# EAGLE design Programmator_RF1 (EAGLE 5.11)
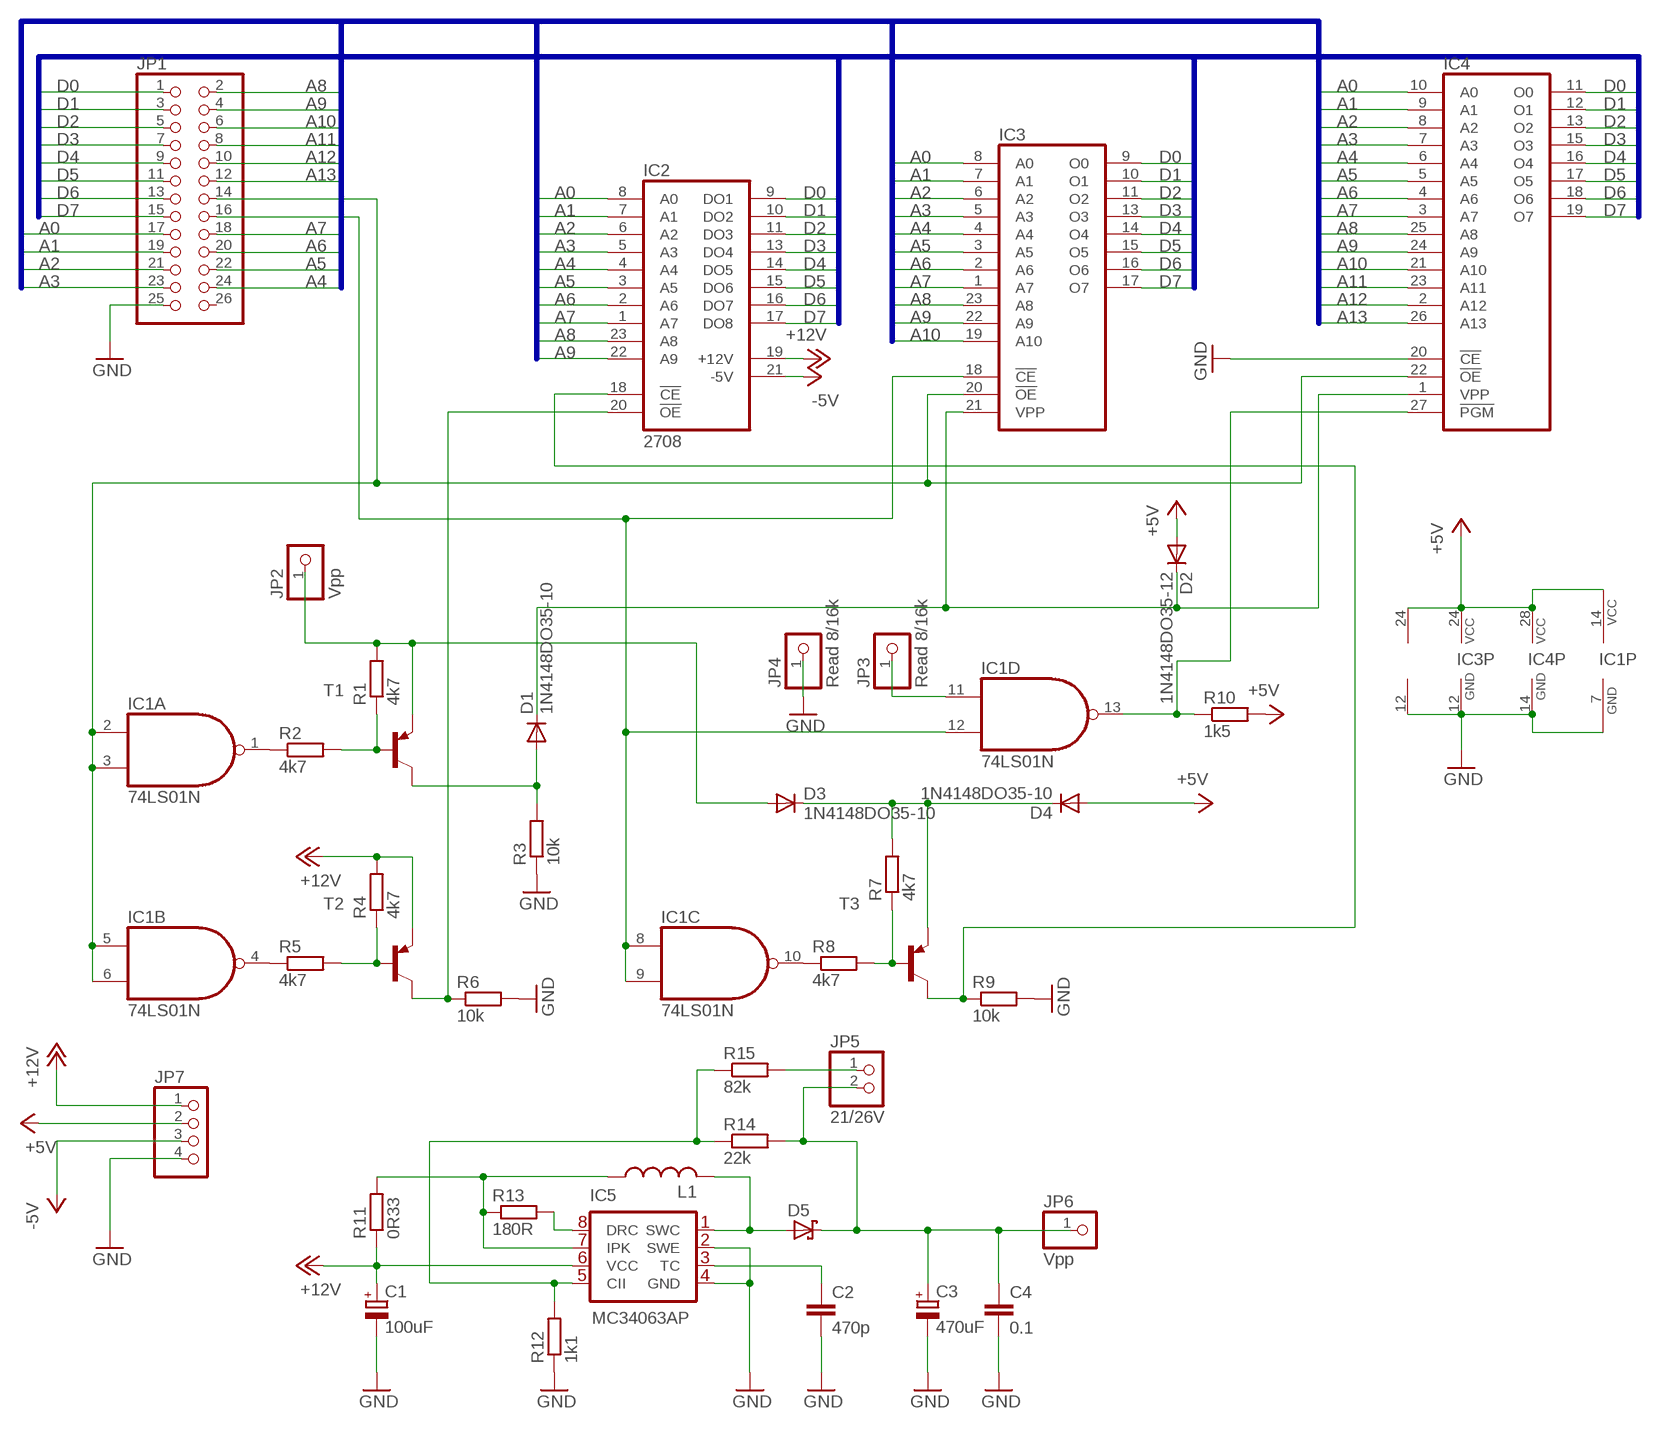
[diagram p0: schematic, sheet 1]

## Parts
C1  100uF  CPOL-EUE2.5-5  [E2,5-5]
C2  470p  C-EU025-024X044  [C025-024X044]
C3  470uF  CPOL-EUE2.5-5  [E2,5-5]
C4  0.1  C-EU025-024X044  [C025-024X044]
D1  1N4148DO35-10  [DO35-10]
D2  1N4148DO35-12  [DO35-12]
D3  1N4148DO35-10  [DO35-10]
D4  1N4148DO35-10  [DO35-10]
D5  SCHOTTKY-DIODEF126Z12  [F126Z12]
IC1  74LS01N  [DIL14]
IC2  2708  [DIL24-6]
IC3  2716  [DIL24]
IC4  27128  [DIL28]
IC5  MC34063AP  [DIL08]
JP1  PINHD-2X13  [2X13]
JP2  Vpp  PINHD-1X1  [1X01]
JP3  Read 8/16k  PINHD-1X1  [1X01]
JP4  Read 8/16k  PINHD-1X1  [1X01]
JP5  21/26V  PINHD-1X2  [1X02]
JP6  Vpp  PINHD-1X1  [1X01]
JP7  PINHD-1X4  [1X04]
L1  L-US0207/10  [0207/10]
R1  4k7  R-EU_0207/10  [0207/10]
R2  4k7  R-EU_0207/10  [0207/10]
R3  10k  R-EU_0207/10  [0207/10]
R4  4k7  R-EU_0207/10  [0207/10]
R5  4k7  R-EU_0207/10  [0207/10]
R6  10k  R-EU_0207/10  [0207/10]
R7  4k7  R-EU_0207/10  [0207/10]
R8  4k7  R-EU_0207/10  [0207/10]
R9  10k  R-EU_0207/10  [0207/10]
R10  1k5  R-EU_0207/10  [0207/10]
R11  0R33  R-EU_0207/10  [0207/10]
R12  1k1  R-EU_0207/10  [0207/10]
R13  180R  R-EU_0207/10  [0207/10]
R14  22k  R-EU_0207/10  [0207/10]
R15  82k  R-EU_0207/10  [0207/10]
T1  -PNP-TO92-CBE  [TO92-CBE]
T2  -PNP-TO92-CBE  [TO92-CBE]
T3  -PNP-TO92-CBE  [TO92-CBE]

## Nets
+5V: D2.A D4.A IC1.14(P:VCC) IC2.24(V+) IC3.24(VCC) IC4.28(VCC) JP7.2 R10.2
+12V: C1.+ IC2.19(+12V) IC5.6(VCC) JP7.1 R4.2 R11.1 T2.E
-5V: IC2.21(-5V) JP7.3
A0: IC2.8(A0) IC3.8(A0) IC4.10(A0) JP1.17
A1: IC2.7(A1) IC3.7(A1) IC4.9(A1) JP1.19
A2: IC2.6(A2) IC3.6(A2) IC4.8(A2) JP1.21
A3: IC2.5(A3) IC3.5(A3) IC4.7(A3) JP1.23
A4: IC2.4(A4) IC3.4(A4) IC4.6(A4) JP1.24
A5: IC2.3(A5) IC3.3(A5) IC4.5(A5) JP1.22
A6: IC2.2(A6) IC3.2(A6) IC4.4(A6) JP1.20
A7: IC2.1(A7) IC3.1(A7) IC4.3(A7) JP1.18
A8: IC2.23(A8) IC3.23(A8) IC4.25(A8) JP1.2
A9: IC2.22(A9) IC3.22(A9) IC4.24(A9) JP1.4
A10: IC3.19(A10) IC4.21(A10) JP1.6
A11: IC4.23(A11) JP1.8
A12: IC4.2(A12) JP1.10
A13: IC4.26(A13) JP1.12
D0: IC2.9(DO1) IC3.9(O0) IC4.11(O0) JP1.1
D1: IC2.10(DO2) IC3.10(O1) IC4.12(O1) JP1.3
D2: IC2.11(DO3) IC3.11(O2) IC4.13(O2) JP1.5
D3: IC2.13(DO4) IC3.13(O3) IC4.15(O3) JP1.7
D4: IC2.14(DO5) IC3.14(O4) IC4.16(O4) JP1.9
D5: IC2.15(DO6) IC3.15(O5) IC4.17(O5) JP1.11
D6: IC2.16(DO7) IC3.16(O6) IC4.18(O6) JP1.13
D7: IC2.17(DO8) IC3.17(O7) IC4.19(O7) JP1.15
GND: C1.- C2.2 C3.- C4.2 IC1.7(P:GND) IC2.12(GND) IC3.12(GND) IC4.14(GND) IC4.20(!CE) IC5.2(SWE) IC5.4(GND) JP1.25 JP4.1 JP7.4 R3.1 R6.2 R9.2 R12.1
N$2: R1.1 R2.2 T1.B
N$3: R4.1 R5.2 T2.B
N$4: R7.1 R8.2 T3.B
N$5: D1.A R3.2 T1.C
N$6: IC1.1(A:O) R2.1
N$7: IC1.13(D:O) IC4.27(!PGM) R10.1
N$8: IC1.4(B:O) R5.1
N$9: IC1.10(C:O) R8.1
N$10: D3.C D4.C R7.2 T3.E
N$11: IC2.18(!CE) R9.1 T3.C
N$12: IC2.20(!OE) R6.1 T2.C
N$13: IC5.7(IPK) L1.1 R11.2 R13.1
N$14: IC1.11(D:I0) JP3.1
N$15: D1.C D2.C IC3.21(VPP) IC4.1(VPP)
N$16: D3.A JP2.1 R1.2 T1.E
N$17: IC1.2(A:I0) IC1.3(A:I1) IC1.5(B:I0) IC1.6(B:I1) IC3.20(!OE) IC4.22(!OE) JP1.14
N$19: IC1.8(C:I0) IC1.9(C:I1) IC1.12(D:I1) IC3.18(!CE) JP1.16
N$20: IC5.5(CII) R12.2 R14.1 R15.1
N$21: IC5.8(DRC) R13.2
N$22: JP5.1 R15.2
N$23: C3.+ C4.1 D5.C JP5.2 JP6.1 R14.2
N$25: C2.1 IC5.3(TC)
N$28: D5.A IC5.1(SWC) L1.2
Unconnected: JP1.26

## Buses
A[0..13]
D[0..7]

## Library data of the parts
C1 C3 = rcl:CPOL-EU: POLARIZED CAPACITOR, European symbol
C2 C4 = rcl:C-EU: CAPACITOR, European symbol
D1-D4 = alex1:1N4148: DIODE
D5 = diode:SCHOTTKY-DIODE: Schottky Diode
IC1 = 74xx-us:74*01: Quad 2-input NAND gate, open collector
IC2 = alex1:2708
IC3 = memory:2716: MEMORY
IC4 = alex1:27128: MEMORY
IC5 = alex1:MC34063A*
JP1 = pinhead:PINHD-2X13: PIN HEADER
JP2-JP4 JP6 = pinhead:PINHD-1X1: PIN HEADER
JP5 = pinhead:PINHD-1X2: PIN HEADER
JP7 = pinhead:PINHD-1X4: PIN HEADER
L1 = rcl:L-US: INDUCTOR, American symbol
R1-R15 = rcl:R-EU_: RESISTOR, European symbol
T1-T3 = transistor-neu-to92:*-PNP-: PNP Transistror

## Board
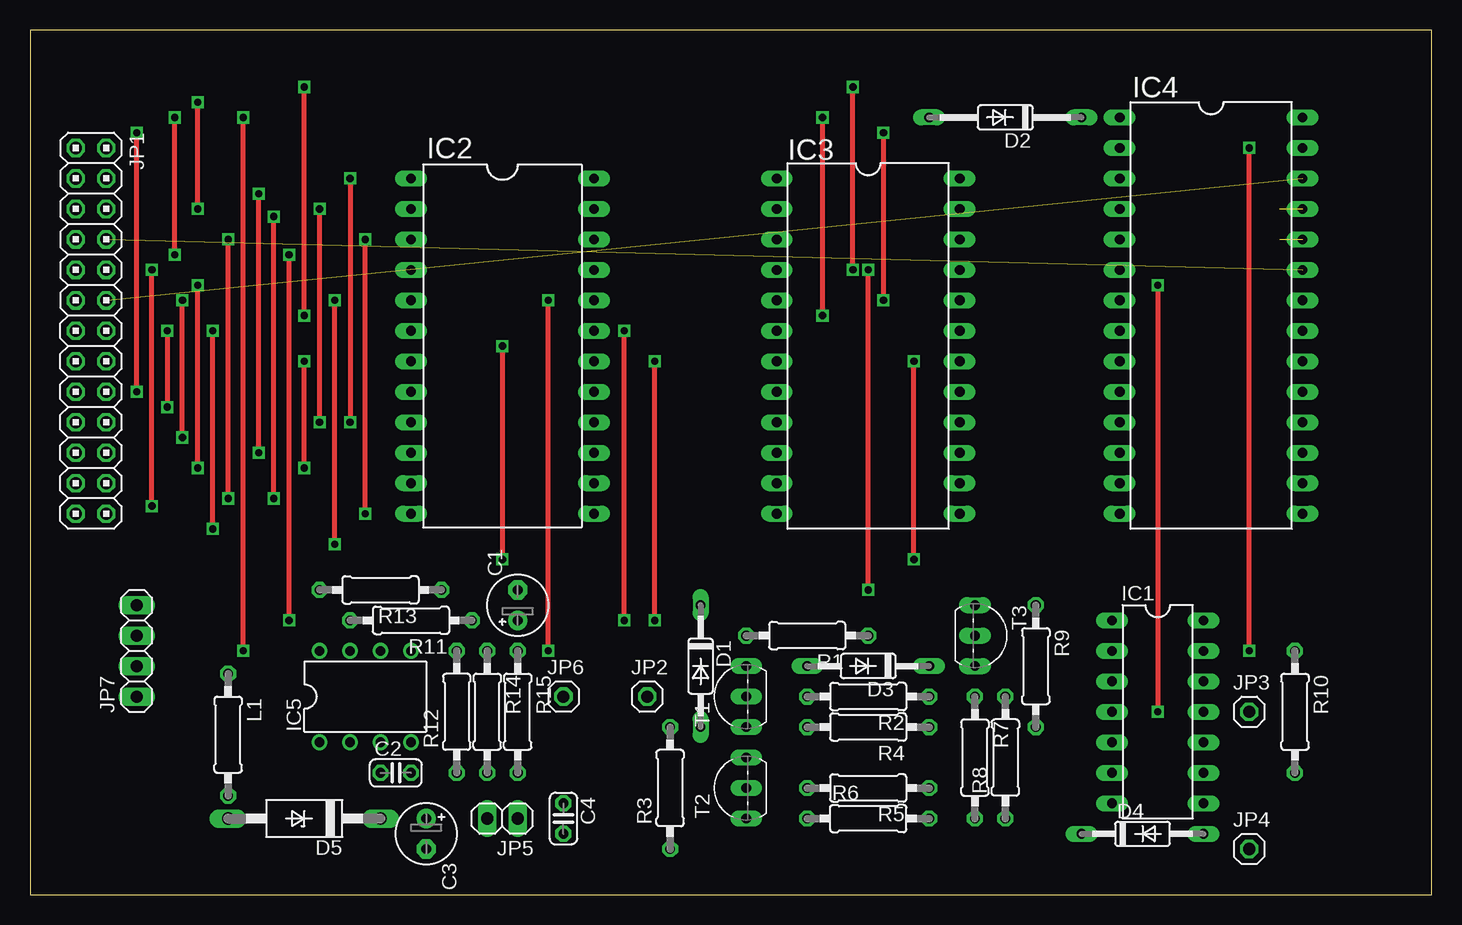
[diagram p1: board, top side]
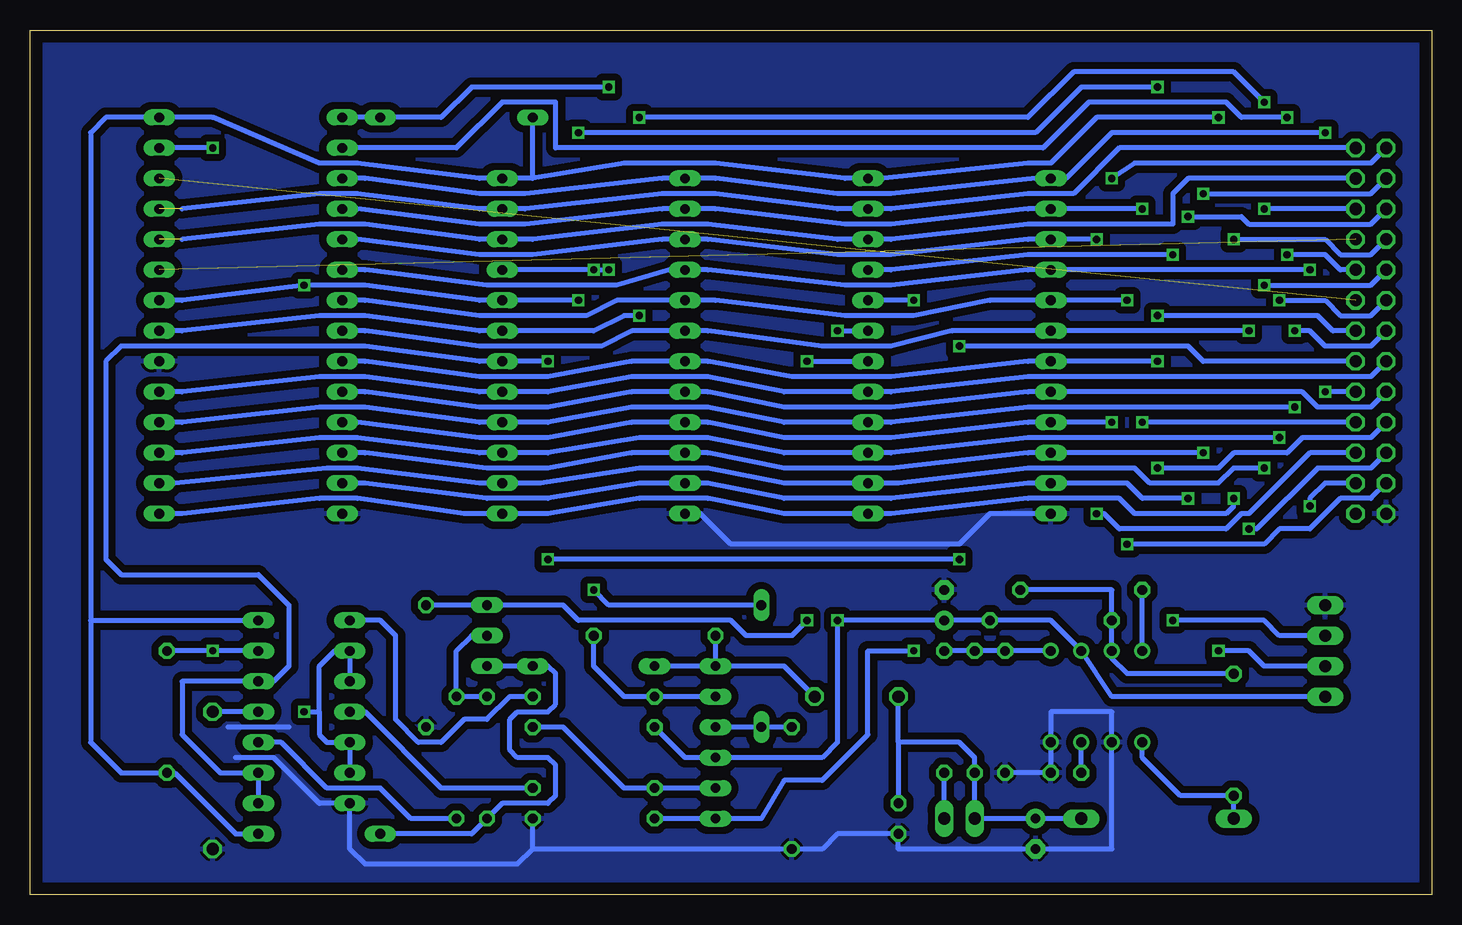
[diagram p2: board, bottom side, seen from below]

Size 116.82 x 72.06 mm. Coordinates in mm from the lower left corner, seen from the top.
Outline: 0,0 116.82,0 116.82,72.06 0,72.06 0,0
Copper layers (1*16): Top 0.035mm / dielectric 1.5mm / Bottom 0.035mm
Design rules "default": minimum track width 10mil, minimum drill 24mil, track to track 8mil, track to pad 8mil, pad to pad 8mil, via to via 8mil, smd to smd 8mil, copper to edge 40mil, drill to drill 8mil, minimum pad ring 10mil, minimum via ring 8mil, stop-mask expansion 4mil, vias tented up to drill 0mil, thermal gap 10mil

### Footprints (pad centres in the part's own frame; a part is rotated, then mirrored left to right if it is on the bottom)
E2,5-5 = drill 0.813 pad 1.6 round: + -1.27,0 | drill 0.813 pad 1.6 octagon: - 1.27,0
C025-024X044 = drill 0.813 octagon: 1 -1.27,0; 2 1.27,0
DO35-10 = drill 0.813 long: A 5.08,0; C -5.08,0
DO35-12 = drill 0.813 long: A 6.35,0; C -6.35,0
F126Z12 = drill 1.016 long: A 6.35,0; C -6.35,0
DIL14 = drill 0.813 long: 1 -7.62,-3.81; 2 -5.08,-3.81; 3 -2.54,-3.81; 4 0,-3.81; 5 2.54,-3.81; 6 5.08,-3.81; 7 7.62,-3.81; 8 7.62,3.81; 9 5.08,3.81; 10 2.54,3.81; 11 0,3.81; 12 -2.54,3.81; 13 -5.08,3.81; 14 -7.62,3.81
DIL24-6 = drill 0.813 long: 1 -13.97,-7.62; 2 -11.43,-7.62; 3 -8.89,-7.62; 4 -6.35,-7.62; 5 -3.81,-7.62; 6 -1.27,-7.62; 7 1.27,-7.62; 8 3.81,-7.62; 9 6.35,-7.62; 10 8.89,-7.62; 11 11.43,-7.62; 12 13.97,-7.62; 13 13.97,7.62; 14 11.43,7.62; 15 8.89,7.62; 16 6.35,7.62; 17 3.81,7.62; 18 1.27,7.62; 19 -1.27,7.62; 20 -3.81,7.62; 21 -6.35,7.62; 22 -8.89,7.62; 23 -11.43,7.62; 24 -13.97,7.62
DIL24 = drill 0.813 long: 1 -13.97,-7.62; 2 -11.43,-7.62; 3 -8.89,-7.62; 4 -6.35,-7.62; 5 -3.81,-7.62; 6 -1.27,-7.62; 7 1.27,-7.62; 8 3.81,-7.62; 9 6.35,-7.62; 10 8.89,-7.62; 11 11.43,-7.62; 12 13.97,-7.62; 13 13.97,7.62; 14 11.43,7.62; 15 8.89,7.62; 16 6.35,7.62; 17 3.81,7.62; 18 1.27,7.62; 19 -1.27,7.62; 20 -3.81,7.62; 21 -6.35,7.62; 22 -8.89,7.62; 23 -11.43,7.62; 24 -13.97,7.62
DIL28 = drill 0.813 long: 1 -16.51,-7.62; 2 -13.97,-7.62; 3 -11.43,-7.62; 4 -8.89,-7.62; 5 -6.35,-7.62; 6 -3.81,-7.62; 7 -1.27,-7.62; 8 1.27,-7.62; 9 3.81,-7.62; 10 6.35,-7.62; 11 8.89,-7.62; 12 11.43,-7.62; 13 13.97,-7.62; 14 16.51,-7.62; 15 16.51,7.62; 16 13.97,7.62; 17 11.43,7.62; 18 8.89,7.62; 19 6.35,7.62; 20 3.81,7.62; 21 1.27,7.62; 22 -1.27,7.62; 23 -3.81,7.62; 24 -6.35,7.62; 25 -8.89,7.62; 26 -11.43,7.62; 27 -13.97,7.62; 28 -16.51,7.62
DIL08 = drill 0.813 pad 1.27 round: 1 -3.81,-3.81; 2 -1.27,-3.81; 3 1.27,-3.81; 4 3.81,-3.81; 5 3.81,3.81; 6 1.27,3.81; 7 -1.27,3.81; 8 -3.81,3.81
2X13 = drill 1.016 octagon: 1 -15.24,-1.27; 2 -15.24,1.27; 3 -12.7,-1.27; 4 -12.7,1.27; 5 -10.16,-1.27; 6 -10.16,1.27; 7 -7.62,-1.27; 8 -7.62,1.27; 9 -5.08,-1.27; 10 -5.08,1.27; 11 -2.54,-1.27; 12 -2.54,1.27; 13 0,-1.27; 14 0,1.27; 15 2.54,-1.27; 16 2.54,1.27; 17 5.08,-1.27; 18 5.08,1.27; 19 7.62,-1.27; 20 7.62,1.27; 21 10.16,-1.27; 22 10.16,1.27; 23 12.7,-1.27; 24 12.7,1.27; 25 15.24,-1.27; 26 15.24,1.27
1X01 = drill 1.016 octagon: 1 0,0
1X02 = drill 1.016 long: 1 -1.27,0; 2 1.27,0
1X04 = drill 1.016 long: 1 -3.81,0; 2 -1.27,0; 3 1.27,0; 4 3.81,0
0207/10 = drill 0.813 octagon: 1 -5.08,0; 2 5.08,0
TO92-CBE = drill 0.813 long: B 0,0; C -2.54,0; E 2.54,0

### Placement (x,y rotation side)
C1  40.64,24.13 90 top
C2  30.48,10.16 0 top
C3  33.02,5.08 270 top
C4  44.45,6.35 270 top
D1  55.88,19.05 270 top
D2  81.28,64.77 180 top
D3  69.85,19.05 180 top
D4  92.71,5.08 0 top
D5  22.86,6.35 180 top
IC1  93.98,15.24 270 top
IC2  39.37,45.72 270 top
IC3  69.85,45.72 270 top
IC4  98.42,48.26 270 top
IC5  27.94,16.51 0 top
JP1  5.08,46.99 270 top
JP2  51.43,16.51 0 top
JP3  101.6,15.24 0 top
JP4  101.6,3.81 0 top
JP5  39.37,6.35 180 top
JP6  44.45,16.51 0 top
JP7  8.89,20.32 90 top
L1  16.51,13.33 270 top
R1  64.77,21.59 180 top
R2  69.85,16.51 180 top
R3  53.34,8.89 90 top
R4  69.85,13.97 180 top
R5  69.85,8.89 180 top
R6  69.85,6.35 0 top
R7  78.74,11.43 270 top
R8  81.28,11.43 90 top
R9  83.82,19.05 270 top
R10  105.41,15.24 270 top
R11  31.75,22.86 180 top
R12  35.56,15.24 90 top
R13  29.21,25.4 180 top
R14  38.1,15.24 270 top
R15  40.64,15.24 270 top
T1  59.69,16.51 90 top
T2  59.69,8.89 90 top
T3  78.74,21.59 270 top

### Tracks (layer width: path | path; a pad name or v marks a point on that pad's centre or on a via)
+5V  (via drill 0.6)
  Top 0.406: v17.78,20.32 v17.78,64.77
  Bottom 0.406: 74.93,59.69 67.31,60.96 59.69,60.96 48.89,59.69 IC2.24 45.72,59.69 33.65,60.96 31.75,60.96 27.94,64.77 v17.78,64.77 | 74.93,59.69 IC3.24 79.38,59.69 89.54,60.96 92.71,60.96 101.6,64.77 IC4.28 110.49,64.77 111.76,63.5 111.76,22.86 | 111.76,22.86 111.76,12.7 109.22,10.16 R10.2 104.78,10.16 99.7,5.08 D4.A | v17.78,20.32 15.24,20.32 13.97,19.05 JP7.2 7.62,19.05 | 74.93,59.69 D2.A | 111.76,22.86 IC1.14
+12V  (via drill 0.6)
  Top 0.406: v49.53,22.86 v49.53,46.99
  Bottom 0.406: R4.2 62.23,11.43 T2.E 50.8,11.43 49.53,12.7 v49.53,22.86 C1.+ R11.1 31.75,22.86 IC5.6 26.67,16.51 JP7.1 | v49.53,46.99 IC2.19
-5V  (via drill 0.6)
  Top 0.406: v21.59,22.86 v21.59,53.34
  Bottom 0.406: IC2.21 45.08,52.07 33.65,53.34 v21.59,53.34 | JP7.3 12.7,21.59 13.97,22.86 v21.59,22.86
A0
  Bottom 0.406: IC2.8 33.65,41.91 45.08,40.64 53.97,40.64 60.32,41.91 IC3.8 66.67,41.91 73.66,40.64 79.38,40.64 88.9,41.91 IC4.10 | IC2.8 30.48,41.91 | JP1.17 5.08,40.64 9.53,40.64 10.79,41.91 IC2.8
A1  (via drill 0.6)
  Top 0.406: v22.86,35.56 v22.86,44.45
  Bottom 0.406: v22.86,44.45 IC2.7 33.65,44.45 45.08,43.18 53.34,43.18 60.32,44.45 IC3.7 66.67,44.45 73.66,43.18 79.38,43.18 88.9,44.45 IC4.9 | JP1.19 5.08,38.1 10.79,38.1 12.07,36.83 16.51,36.83 17.78,35.56 v22.86,35.56
A2  (via drill 0.6)
  Top 0.406: v15.24,30.48 v15.24,46.99
  Bottom 0.406: IC4.8 88.9,46.99 79.38,45.72 69.22,45.72 66.67,46.99 IC3.6 60.32,46.99 50.8,45.72 45.08,45.72 40,46.99 IC2.6 v15.24,46.99 | JP1.21 5.08,35.56 9.53,35.56 14.61,30.48 v15.24,30.48
A3  (via drill 0.6)
  Top 0.406: v25.4,29.21 v25.4,49.53
  Bottom 0.406: v25.4,49.53 IC2.5 36.83,49.53 43.18,48.26 48.89,48.26 59.69,49.53 IC3.5 67.95,49.53 70.48,48.26 79.38,48.26 88.9,49.53 IC4.7 | JP1.23 5.08,33.02 7.62,33.02 10.16,30.48 12.7,30.48 13.97,29.21 v25.4,29.21
A4  (via drill 0.6)
  Top 0.406: v10.16,32.39 v10.16,52.07
  Bottom 0.406: v10.16,52.07 IC2.4 33.65,52.07 45.08,50.8 48.89,50.8 60.32,52.07 IC3.4 63.5,52.07 67.95,50.8 78.74,50.8 88.9,52.07 IC4.6 | JP1.24 8.89,34.29 10.16,33.02 v10.16,32.39
A5  (via drill 0.6)
  Top 0.406: v27.94,31.75 v27.94,54.61
  Bottom 0.406: v27.94,54.61 IC2.3 33.65,54.61 45.08,53.34 49.53,53.34 60.32,54.61 IC3.3 64.14,54.61 74.93,53.34 79.38,53.34 89.54,54.61 IC4.5 | JP1.22 10.16,36.83 15.24,31.75 15.88,31.75 17.14,30.48 26.04,30.48 27.3,31.75 v27.94,31.75
A6  (via drill 0.6)
  Top 0.406: v24.13,39.37 v24.13,57.15
  Bottom 0.406: v24.13,57.15 IC2.2 33.65,57.15 45.08,55.88 48.89,55.88 59.69,57.15 IC3.2 64.14,57.15 75.56,55.88 79.38,55.88 89.54,57.15 IC4.4 | JP1.20 v24.13,39.37
A7  (via drill 0.6)
  Top 0.406: v8.89,41.91 v8.89,63.5
  Bottom 0.406: IC4.3 88.9,59.69 79.38,58.42 75.56,58.42 64.14,59.69 IC3.1 59.69,59.69 49.53,58.42 45.08,58.42 33.02,59.69 IC2.1 30.48,59.69 26.67,63.5 v8.89,63.5 | JP1.18 v8.89,41.91
A8  (1 unrouted)
  Bottom 0.406: 104.14,57.15 92.71,58.42 89.54,58.42 79.38,57.15 IC3.23 75.56,57.15 64.14,58.42 59.69,58.42 49.53,57.15 IC2.23 45.08,57.15 33.65,58.42 29.84,58.42 26.04,62.23 JP1.2
A9  (1 unrouted)
  Bottom 0.406: 104.14,54.61 92.71,55.88 88.9,55.88 79.38,54.61 IC3.22 74.93,54.61 64.14,55.88 60.32,55.88 49.53,54.61 IC2.22 45.08,54.61 33.65,55.88 21.59,55.88 21.59,58.42 20.32,59.69 JP1.4
A10  (via drill 0.6)
  Top 0.406: v13.97,57.15 v13.97,66.04 | v66.04,64.77 v66.04,48.26
  Bottom 0.406: IC3.19 79.38,46.99 88.9,48.26 92.71,48.26 104.14,46.99 IC4.21 | IC3.19 76.2,46.99 | v13.97,66.04 16.51,68.58 29.84,68.58 33.65,64.77 v66.04,64.77 | v66.04,48.26 67.31,48.26 69.85,46.99 IC3.19 | JP1.6 v13.97,57.15
A11  (1 unrouted)
A12  (via drill 0.6)
  Top 0.406: v12.07,53.34 v12.07,64.77
  Bottom 0.406: v12.07,64.77 15.88,64.77 17.14,66.04 28.57,66.04 32.38,62.23 73.03,62.23 73.03,66.04 77.47,66.04 81.28,62.23 IC4.2 | JP1.10 7.62,52.07 8.89,53.34 v12.07,53.34
A13  (1 unrouted)
D0  (via drill 0.6)
  Top 0.406: v26.67,59.69 v26.67,39.37
  Bottom 0.406: v26.67,39.37 IC2.9 33.65,39.37 45.08,38.1 53.97,38.1 60.32,39.37 IC3.9 66.67,39.37 73.66,38.1 79.38,38.1 89.54,39.37 IC4.11 | JP1.1 5.08,60.96 24.77,60.96 v26.67,59.69
D1  (via drill 0.6)
  Top 0.406: v19.05,36.83 v19.05,58.42
  Bottom 0.406: v19.05,36.83 IC2.10 33.65,36.83 45.08,35.56 53.97,35.56 60.32,36.83 IC3.10 66.67,36.83 73.66,35.56 78.74,35.56 88.9,36.83 IC4.12 | JP1.3 5.08,58.42 v19.05,58.42
D2  (via drill 0.6)
  Top 0.406: v20.32,33.02 v20.32,56.52
  Bottom 0.406: IC4.13 88.9,34.29 78.74,33.02 73.66,33.02 66.04,34.29 IC3.11 60.32,34.29 53.97,33.02 45.08,33.02 33.65,34.29 IC2.11 25.4,34.29 24.13,33.02 v20.32,33.02 | JP1.5 5.08,55.88 15.24,55.88 15.88,56.52 v20.32,56.52
D3  (via drill 0.6)
  Top 0.406: v16.51,33.02 v16.51,54.61
  Bottom 0.406: IC4.15 104.14,31.75 92.71,33.02 89.54,33.02 80.65,31.75 IC3.13 73.66,31.75 66.04,33.02 60.32,33.02 53.97,31.75 IC2.13 45.08,31.75 33.65,33.02 26.04,33.02 24.77,31.75 17.14,31.75 16.51,32.39 v16.51,33.02 | JP1.7 5.08,53.34 7.62,53.34 8.89,54.61 v16.51,54.61
D4  (via drill 0.6)
  Top 0.406: v13.97,35.56 v13.97,50.8
  Bottom 0.406: IC4.16 104.78,34.29 92.08,35.56 89.54,35.56 79.38,34.29 IC3.14 74.3,34.29 66.04,35.56 60.32,35.56 53.97,34.29 IC2.14 44.45,34.29 33.65,35.56 24.77,35.56 23.5,34.29 17.78,34.29 16.51,35.56 v13.97,35.56 | JP1.9 5.08,50.8 v13.97,50.8
D5  (via drill 0.6)
  Top 0.406: v12.7,38.1 v12.7,49.53
  Bottom 0.406: v12.7,38.1 33.65,38.1 45.08,36.83 IC2.15 53.97,36.83 60.32,38.1 66.04,38.1 73.66,36.83 IC3.15 79.38,36.83 89.54,38.1 92.71,38.1 104.14,36.83 IC4.17 | JP1.11 5.08,48.26 7.62,48.26 8.89,49.53 v12.7,49.53
D6  (via drill 0.6)
  Top 0.406: v11.43,46.99 v11.43,40.64
  Bottom 0.406: v11.43,40.64 33.65,40.64 45.08,39.37 IC2.16 53.97,39.37 60.32,40.64 66.67,40.64 73.66,39.37 IC3.16 79.38,39.37 88.9,40.64 92.71,40.64 104.14,39.37 IC4.18 | JP1.13 5.08,45.72 8.89,45.72 10.16,46.99 v11.43,46.99
D7
  Bottom 0.406: IC4.19 104.14,41.91 92.71,43.18 88.9,43.18 79.38,41.91 IC3.17 73.66,41.91 66.67,43.18 60.32,43.18 53.97,41.91 IC2.17 45.08,41.91 33.65,43.18 5.08,43.18 JP1.15
GND
  Bottom 0.406: IC2.12 36.83,31.75 39.37,29.21 58.42,29.21 60.96,31.75 IC3.12 | 74.93,3.81 76.2,2.54 88.9,2.54 90.17,3.81 IC1.7 92.71,7.62 96.52,11.43 99.7,11.43 | 74.93,3.81 R3.1 50.8,3.81 49.53,5.08 C4.2 44.45,3.81 C3.- 26.67,3.81 IC5.2 26.67,15.24 31.75,15.24 IC5.4 C2.2 R12.1 | 74.93,3.81 R6.2 | 95.25,13.97 100.33,13.97
  pour Bottom (isolate 0.61): 0,72.39 116.84,72.39 116.84,0 0,0
N$2
  Bottom 0.406: T1.B R2.2 67.31,16.51 69.85,19.05 R1.1
N$3
  Bottom 0.406: T2.B R5.2 67.31,8.89 72.39,13.97 R4.1
N$4
  Bottom 0.406: R7.1 R8.2 81.28,20.32 80.01,21.59 T3.B
N$5
  Bottom 0.406: D1.A R3.2 T1.C
N$6
  Bottom 0.406: R2.1 76.84,16.51 78.74,14.6 80.65,14.6 82.55,12.7 84.45,12.7 86.36,14.6 86.36,21.59 87.63,22.86 IC1.1
N$7  (via drill 0.6)
  Top 0.406: v101.6,20.32 v101.6,62.23
  Bottom 0.406: IC1.13 v101.6,20.32 R10.1 | v101.6,62.23 IC4.27
N$8
  Bottom 0.406: R5.1 82.55,8.89 88.9,15.24 IC1.4
N$9
  Bottom 0.406: R8.1 85.09,6.35 87.63,8.89 92.08,8.89 95.89,12.7 IC1.10 98.42,12.7
N$10
  Bottom 0.406: D4.C 80.01,5.08 R7.2 77.47,7.62 73.66,7.62 73.03,8.26 73.03,10.79 73.66,11.43 76.2,11.43 76.84,12.06 76.84,14.6 76.2,15.24 73.66,15.24 73.03,15.87 73.03,18.41 73.66,19.05 D3.C T3.E
N$11  (via drill 0.6)
  Top 0.406: v52.07,22.86 v52.07,44.45
  Bottom 0.406: R9.1 T3.C 72.39,24.13 71.12,22.86 58.42,22.86 57.15,21.59 53.34,21.59 v52.07,22.86 | v52.07,44.45 IC2.18
N$12  (via drill 0.6)
  Top 0.406: v43.18,20.32 v43.18,49.53
  Bottom 0.406: R6.1 T2.C 55.88,6.35 53.97,9.53 50.8,9.53 46.99,13.33 46.99,20.32 v43.18,20.32 | v43.18,49.53 IC2.20
N$13
  Bottom 0.406: R13.1 26.67,25.4 R11.2 IC5.7 26.67,19.69 25.4,18.41 L1.1
N$14
  Bottom 0.406: IC1.11 JP3.1
N$15  (via drill 0.6)
  Top 0.406: v69.85,25.4 v69.85,52.07 | v68.58,52.07 v68.58,67.31
  Bottom 0.406: D1.C 68.58,24.13 v69.85,25.4 | IC3.21 v69.85,52.07 v68.58,52.07 | v68.58,67.31 80.01,67.31 82.55,64.77 D2.C IC4.1
N$16
  Bottom 0.406: T1.E R1.2 | T1.E D3.A | T1.E 53.97,19.05 JP2.1
N$17  (via drill 0.6)
  Top 0.406: v93.98,50.8 v93.98,15.24 | v71.12,63.5 v71.12,49.53 | v22.86,48.26 v22.86,67.31
  Bottom 0.406: IC1.6 IC1.5 92.08,12.7 92.71,13.33 92.71,15.24 | IC1.3 IC1.2 91.44,20.32 92.71,19.05 92.71,15.24 | v71.12,49.53 IC3.20 79.38,49.53 88.9,50.8 v93.98,50.8 104.14,49.53 IC4.22 | v71.12,63.5 33.02,63.5 29.21,67.31 v22.86,67.31 | JP1.14 8.26,46.99 9.53,48.26 v22.86,48.26 | v93.98,15.24 92.71,15.24
N$19  (via drill 0.6)
  Top 0.406: v39.37,45.72 v39.37,27.94 | v73.66,27.94 v73.66,44.45
  Bottom 0.406: IC1.8 IC1.9 100.97,10.16 104.14,13.33 104.14,17.78 IC1.12 96.52,17.78 95.25,19.05 95.25,24.13 97.79,26.67 109.22,26.67 110.49,27.94 110.49,44.45 109.22,45.72 88.9,45.72 79.38,44.45 IC3.18 v73.66,44.45 | v39.37,27.94 v73.66,27.94 | JP1.16 19.05,44.45 20.32,45.72 v39.37,45.72
N$20
  Bottom 0.406: IC5.5 R12.2 R14.1 R15.1
N$21
  Bottom 0.406: IC5.8 R13.2
N$22
  Bottom 0.406: JP5.1 R15.2
N$23
  Bottom 0.406: D5.C C3.+ JP5.2 R14.2 38.1,11.43 39.37,12.7 44.45,12.7 | 44.45,12.7 JP6.1 | 44.45,12.7 C4.1
N$25
  Bottom 0.406: C2.1 IC5.3
N$28
  Bottom 0.406: D5.A L1.2 20.96,8.26 24.13,11.43 IC5.1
